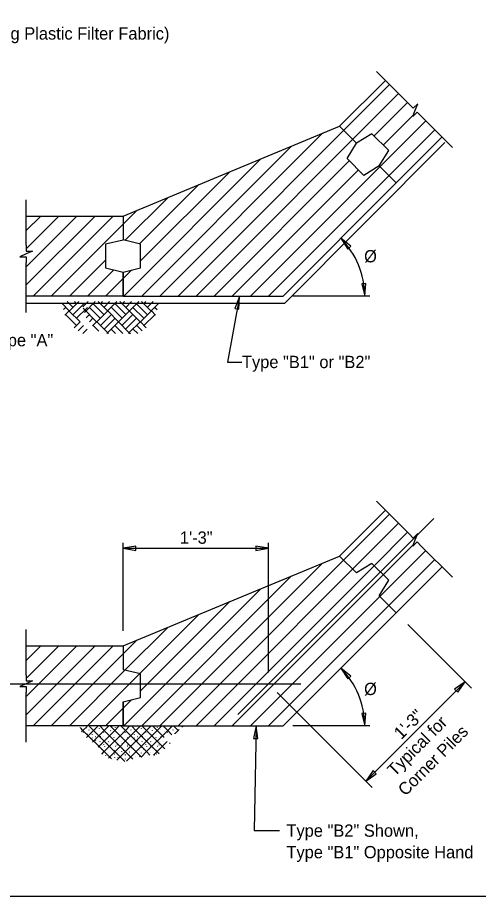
# Model space of a CAD drawing. Extents: x 111162.5 to 111216.6, y 110741.1 to 110776.1.
# Drawn here: x 111173.58 to 111179.25, y 110754.44 to 110765.24 of the extents above; entities that cross this region are included whole.
import ezdxf

# ---------------------------------------------------------------- set-up
doc = ezdxf.new("R2010")
doc.units = 0
for name, color, linetype in [('Patterning', 7, 'Continuous'), ('PlotBorder_dp', 7, 'Continuous'), ('SheetBorder_dp', 7, 'Continuous'), ('TextMisc', 7, 'Continuous'), ('Viewport', 7, 'Continuous')]:
    doc.layers.add(name, color=color, linetype=linetype)

msp = doc.modelspace()

# ---------------------------------------------------------------- linework, layer by layer
at = {"layer": 'Patterning'}
for p, q in [((111177.998, 110764.581), (111178.4, 110764.179)), ((111178.549, 110764.03), (111178.931, 110763.648)), ((111176.868, 110761.733), (111178.84, 110763.706)), ((111173.687, 110762.444), (111173.687, 110763.004)), ((111173.687, 110761.618), (111173.687, 110762.233)), ((111173.687, 110761.733), (111176.868, 110761.733)), ((111177.916, 110761.819), (111176.967, 110761.819)), ((111177.998, 110759.297), (111178.4, 110758.895)), ((111174.879, 110757.705), (111174.879, 110758.784)), ((111174.879, 110758.718), (111176.669, 110758.718)), ((111176.669, 110757.192), (111176.669, 110758.784)), ((111178.549, 110758.746), (111178.931, 110758.364)), ((111178.385, 110757.782), (111179.167, 110756.999)), ((111173.687, 110757.16), (111173.687, 110757.72)), ((111177.866, 110755.855), (111179.089, 110757.078)), ((111173.687, 110756.333), (111173.687, 110756.949)), ((111176.774, 110756.947), (111177.945, 110755.777)), ((111177.916, 110756.535), (111176.967, 110756.535))]:
    msp.add_line(p, q, dxfattribs=at)
for points in [[(111178.549, 110764.03), (111178.498, 110764.082), (111178.443, 110764.027), (111178.474, 110764.105), (111178.505, 110764.184), (111178.45, 110764.129), (111178.399, 110764.181)], [(111173.687, 110762.444), (111173.687, 110762.371), (111173.765, 110762.371), (111173.687, 110762.337), (111173.61, 110762.304), (111173.687, 110762.304), (111173.687, 110762.231)], [(111176.31, 110761.815), (111176.164, 110761.007), (111176.341, 110761.007)], [(111178.549, 110758.746), (111178.498, 110758.797), (111178.443, 110758.743), (111178.474, 110758.821), (111178.505, 110758.9), (111178.45, 110758.845), (111178.399, 110758.896)], [(111173.687, 110757.159), (111173.687, 110757.087), (111173.765, 110757.087), (111173.687, 110757.053), (111173.61, 110757.019), (111173.687, 110757.019), (111173.687, 110756.947)], [(111176.517, 110756.535), (111176.493, 110755.249), (111176.804, 110755.249)]]:
    msp.add_lwpolyline(points, dxfattribs=at)
for points in [[(111177.559, 110762.53), (111177.643, 110762.397), (111177.683, 110762.432)], [(111177.854, 110761.819), (111177.868, 110761.976), (111177.816, 110761.972)], [(111176.31, 110761.815), (111176.254, 110761.667), (111176.305, 110761.657)], [(111174.879, 110758.718), (111175.035, 110758.692), (111175.035, 110758.744)], [(111176.669, 110758.718), (111176.513, 110758.744), (111176.513, 110758.692)], [(111177.559, 110757.246), (111177.643, 110757.112), (111177.683, 110757.148)], [(111179.089, 110757.078), (111178.959, 110756.986), (111178.997, 110756.949)], [(111177.854, 110756.534), (111177.868, 110756.692), (111177.816, 110756.688)], [(111176.517, 110756.535), (111176.486, 110756.38), (111176.539, 110756.378)], [(111177.866, 110755.855), (111177.995, 110755.947), (111177.958, 110755.985)]]:
    msp.add_lwpolyline(points, close=True, dxfattribs=at)
for centre in [(111176.847, 110761.819), (111176.847, 110756.535)]:
    msp.add_arc(centre, 1.005, 0, 45.0008, dxfattribs=at)
at = {"layer": 'PlotBorder_dp'}
for p, q in [((111177.543, 110763.908), (111178.107, 110764.472)), ((111174.879, 110762.804), (111177.543, 110763.908)), ((111177.543, 110763.908), (111177.752, 110763.699)), ((111177.752, 110763.699), (111177.543, 110763.908)), ((111177.543, 110763.908), (111177.752, 110763.699)), ((111177.942, 110763.816), (111177.752, 110763.699)), ((111178.148, 110763.61), (111177.942, 110763.816)), ((111177.635, 110763.509), (111177.752, 110763.699)), ((111178.804, 110763.776), (111178.239, 110763.212)), ((111178.031, 110763.42), (111178.148, 110763.61)), ((111177.841, 110763.303), (111177.635, 110763.509)), ((111178.031, 110763.42), (111177.841, 110763.303)), ((111178.031, 110763.42), (111178.239, 110763.212)), ((111178.239, 110763.212), (111178.031, 110763.42)), ((111178.239, 110763.212), (111178.031, 110763.42)), ((111176.847, 110761.819), (111178.239, 110763.212)), ((111173.687, 110762.804), (111174.879, 110762.804)), ((111174.879, 110762.804), (111174.879, 110762.509)), ((111174.879, 110762.804), (111174.879, 110762.508)), ((111174.879, 110762.508), (111174.662, 110762.457)), ((111175.095, 110762.457), (111174.879, 110762.509)), ((111174.662, 110762.457), (111174.662, 110762.166)), ((111175.095, 110762.166), (111175.095, 110762.457)), ((111174.662, 110762.166), (111174.879, 110762.115)), ((111174.879, 110762.115), (111175.095, 110762.166)), ((111174.879, 110762.115), (111174.879, 110761.819)), ((111174.879, 110761.819), (111174.879, 110762.115)), ((111174.879, 110761.819), (111173.687, 110761.819)), ((111174.879, 110761.819), (111176.847, 110761.819)), ((111177.543, 110758.623), (111178.107, 110759.188)), ((111174.879, 110757.52), (111177.543, 110758.623)), ((111177.543, 110758.623), (111177.752, 110758.415)), ((111177.752, 110758.415), (111177.543, 110758.623)), ((111177.543, 110758.623), (111177.752, 110758.415)), ((111177.942, 110758.532), (111177.752, 110758.415)), ((111178.148, 110758.326), (111177.942, 110758.532)), ((111178.804, 110758.491), (111178.239, 110757.927)), ((111178.031, 110758.136), (111178.148, 110758.326)), ((111178.031, 110758.136), (111178.239, 110757.927)), ((111178.239, 110757.927), (111178.031, 110758.136)), ((111178.239, 110757.927), (111178.031, 110758.136)), ((111176.847, 110756.535), (111178.239, 110757.927)), ((111173.687, 110757.52), (111174.879, 110757.52)), ((111174.879, 110757.52), (111174.879, 110757.224)), ((111174.879, 110757.52), (111174.879, 110757.224)), ((111175.095, 110757.173), (111174.879, 110757.224)), ((111175.095, 110756.882), (111175.095, 110757.173)), ((111174.879, 110756.831), (111175.095, 110756.882)), ((111174.879, 110756.831), (111174.879, 110756.535)), ((111174.879, 110756.535), (111174.879, 110756.831)), ((111174.879, 110756.535), (111173.687, 110756.535)), ((111174.879, 110756.535), (111176.847, 110756.535))]:
    msp.add_line(p, q, dxfattribs=at)
at = {"layer": 'TextMisc'}
for p, q in [((111175.555, 110761.819), (111178.157, 110764.422)), ((111175.778, 110761.819), (111178.269, 110764.31)), ((111177.969, 110763.788), (111178.38, 110764.199)), ((111178.08, 110763.677), (111178.452, 110764.048)), ((111176.446, 110761.819), (111178.603, 110763.976)), ((111175.332, 110761.819), (111177.333, 110763.821)), ((111176.669, 110761.819), (111178.714, 110763.865)), ((111175.109, 110761.819), (111176.953, 110763.663)), ((111174.887, 110761.819), (111176.573, 110763.506)), ((111176, 110761.819), (111177.663, 110763.482)), ((111175.095, 110762.251), (111176.193, 110763.348)), ((111176.223, 110761.819), (111177.774, 110763.371)), ((111175.082, 110762.46), (111175.812, 110763.191)), ((111174.902, 110762.503), (111175.432, 110763.033)), ((111173.996, 110761.819), (111175.052, 110762.876)), ((111173.687, 110762.179), (111174.312, 110762.804)), ((111173.687, 110761.956), (111174.535, 110762.804)), ((111173.687, 110762.625), (111173.866, 110762.804)), ((111173.687, 110762.402), (111174.089, 110762.804)), ((111173.773, 110761.819), (111174.757, 110762.804)), ((111174.218, 110761.819), (111174.662, 110762.263)), ((111174.441, 110761.819), (111174.764, 110762.142)), ((111174.664, 110761.819), (111174.984, 110762.14)), ((111174.128, 110761.729), (111174.217, 110761.639)), ((111174.193, 110761.751), (111174.261, 110761.683)), ((111174.335, 110761.751), (111174.22, 110761.637)), ((111174.396, 110761.724), (111174.264, 110761.592)), ((111174.282, 110761.751), (111174.306, 110761.728)), ((111174.383, 110761.686), (111174.448, 110761.751)), ((111174.537, 110761.751), (111174.403, 110761.617)), ((111174.51, 110761.724), (111174.642, 110761.592)), ((111174.571, 110761.751), (111174.686, 110761.637)), ((111174.624, 110761.751), (111174.601, 110761.728)), ((111174.713, 110761.751), (111174.645, 110761.683)), ((111174.801, 110761.751), (111174.689, 110761.639)), ((111174.78, 110761.725), (111174.913, 110761.592)), ((111175.072, 110761.751), (111174.824, 110761.504)), ((111174.841, 110761.751), (111175.089, 110761.504)), ((111174.868, 110761.724), (111174.895, 110761.751)), ((111174.912, 110761.68), (111174.983, 110761.751)), ((111175.045, 110761.724), (111175.177, 110761.592)), ((111175.106, 110761.751), (111175.221, 110761.637)), ((111175.159, 110761.751), (111175.136, 110761.728)), ((111175.248, 110761.751), (111175.18, 110761.683)), ((111175.314, 110761.729), (111175.224, 110761.639)), ((111174.17, 110761.681), (111174.145, 110761.655)), ((111174.214, 110761.637), (111174.161, 110761.583)), ((111174.35, 110761.501), (111174.217, 110761.634)), ((111174.441, 110761.68), (111174.308, 110761.548)), ((111174.388, 110761.67), (111174.554, 110761.504)), ((111174.466, 110761.68), (111174.598, 110761.548)), ((111174.556, 110761.501), (111174.689, 110761.634)), ((111174.692, 110761.637), (111174.824, 110761.504)), ((111174.736, 110761.681), (111174.869, 110761.548)), ((111175.001, 110761.68), (111175.133, 110761.548)), ((111175.092, 110761.501), (111175.224, 110761.634)), ((111175.227, 110761.637), (111175.28, 110761.583)), ((111175.271, 110761.681), (111175.297, 110761.655)), ((111174.306, 110761.457), (111174.173, 110761.589)), ((111174.465, 110761.592), (111174.426, 110761.553)), ((111174.509, 110761.548), (111174.464, 110761.503)), ((111174.601, 110761.457), (111174.733, 110761.589)), ((111174.645, 110761.413), (111174.777, 110761.545)), ((111175, 110761.592), (111174.868, 110761.46)), ((111175.045, 110761.548), (111174.912, 110761.416)), ((111175.136, 110761.457), (111175.268, 110761.589)), ((111174.35, 110761.501), (111174.276, 110761.428)), ((111174.394, 110761.457), (111174.328, 110761.392)), ((111174.438, 110761.413), (111174.382, 110761.358)), ((111174.554, 110761.504), (111174.503, 110761.453)), ((111174.513, 110761.457), (111174.582, 110761.388)), ((111174.556, 110761.501), (111174.698, 110761.359)), ((111174.822, 110761.501), (111174.678, 110761.358)), ((111174.733, 110761.413), (111174.788, 110761.358)), ((111174.777, 110761.457), (111174.876, 110761.358)), ((111174.822, 110761.501), (111174.954, 110761.369)), ((111175.089, 110761.504), (111174.956, 110761.372)), ((111175.004, 110761.413), (111175.059, 110761.358)), ((111175.048, 110761.457), (111175.113, 110761.392)), ((111175.092, 110761.501), (111175.165, 110761.428)), ((111174.948, 110761.358), (111174.956, 110761.366)), ((111174.959, 110761.369), (111174.971, 110761.358)), ((111175.555, 110756.535), (111178.157, 110759.138)), ((111175.778, 110756.535), (111178.269, 110759.026)), ((111178.701, 110759.085), (111176.291, 110756.675)), ((111177.969, 110758.504), (111178.38, 110758.915)), ((111178.08, 110758.393), (111178.452, 110758.764)), ((111176, 110756.535), (111178.086, 110758.62)), ((111176.446, 110756.535), (111178.603, 110758.692)), ((111175.332, 110756.535), (111177.333, 110758.536)), ((111176.669, 110756.535), (111178.714, 110758.581)), ((111175.109, 110756.535), (111176.953, 110758.379)), ((111176.223, 110756.535), (111178.08, 110758.393)), ((111174.887, 110756.535), (111176.573, 110758.221)), ((111175.095, 110756.967), (111176.193, 110758.064)), ((111175.082, 110757.176), (111175.812, 110757.906)), ((111174.902, 110757.219), (111175.432, 110757.749)), ((111173.687, 110756.895), (111174.312, 110757.52)), ((111173.687, 110756.672), (111174.535, 110757.52)), ((111173.687, 110757.34), (111173.866, 110757.52)), ((111173.687, 110757.118), (111174.089, 110757.52)), ((111173.773, 110756.535), (111174.757, 110757.52)), ((111173.996, 110756.535), (111175.052, 110757.591)), ((111174.218, 110756.535), (111174.902, 110757.219)), ((111174.441, 110756.535), (111175.095, 110757.189)), ((111173.293, 110757.053), (111173.687, 110757.053)), ((111173.687, 110757.053), (111177.065, 110757.053)), ((111174.664, 110756.535), (111174.984, 110756.856)), ((111174.356, 110756.517), (111174.356, 110756.52)), ((111174.386, 110756.479), (111174.358, 110756.507)), ((111174.369, 110756.461), (111174.386, 110756.479)), ((111174.386, 110756.479), (111174.437, 110756.529)), ((111174.647, 110756.218), (111174.386, 110756.479)), ((111174.393, 110756.453), (111174.394, 110756.456)), ((111174.428, 110756.509), (111174.426, 110756.51)), ((111174.429, 110756.392), (111174.517, 110756.479)), ((111174.441, 110756.436), (111174.437, 110756.435)), ((111174.462, 110756.482), (111174.459, 110756.481)), ((111174.517, 110756.479), (111174.466, 110756.529)), ((111174.483, 110756.438), (111174.481, 110756.44)), ((111174.494, 110756.501), (111174.493, 110756.502)), ((111174.501, 110756.333), (111174.647, 110756.479)), ((111174.501, 110756.431), (111174.503, 110756.434)), ((111174.517, 110756.479), (111174.567, 110756.53)), ((111174.647, 110756.349), (111174.517, 110756.479)), ((111174.531, 110756.484), (111174.531, 110756.487)), ((111174.588, 110756.5), (111174.589, 110756.503)), ((111174.647, 110756.479), (111174.596, 110756.53)), ((111174.618, 110756.44), (111174.618, 110756.443)), ((111174.624, 110756.493), (111174.625, 110756.496)), ((111174.643, 110756.455), (111174.644, 110756.458)), ((111174.647, 110756.479), (111174.698, 110756.53)), ((111175.001, 110756.124), (111174.647, 110756.479)), ((111174.647, 110756.218), (111174.907, 110756.479)), ((111174.647, 110756.349), (111174.777, 110756.479)), ((111174.698, 110756.139), (111175.037, 110756.479)), ((111174.725, 110756.474), (111174.727, 110756.477)), ((111174.725, 110756.426), (111174.727, 110756.429)), ((111174.777, 110756.479), (111174.726, 110756.53)), ((111174.745, 110756.525), (111174.741, 110756.524)), ((111174.769, 110756.44), (111174.769, 110756.443)), ((111174.777, 110756.479), (111174.829, 110756.53)), ((111175.104, 110756.152), (111174.777, 110756.479)), ((111174.787, 110756.512), (111174.786, 110756.514)), ((111174.787, 110756.465), (111174.786, 110756.466)), ((111174.801, 110756.112), (111175.168, 110756.479)), ((111174.818, 110756.489), (111174.818, 110756.492)), ((111174.907, 110756.479), (111174.856, 110756.531)), ((111174.872, 110756.516), (111174.873, 110756.52)), ((111174.872, 110756.469), (111174.873, 110756.472)), ((111174.907, 110756.479), (111174.959, 110756.531)), ((111175.168, 110756.218), (111174.907, 110756.479)), ((111174.91, 110756.453), (111174.911, 110756.456)), ((111174.945, 110756.509), (111174.943, 110756.51)), ((111174.957, 110756.436), (111174.954, 110756.435)), ((111174.979, 110756.482), (111174.976, 110756.481)), ((111175.037, 110756.479), (111174.985, 110756.531)), ((111175, 110756.438), (111174.998, 110756.44)), ((111175.011, 110756.501), (111175.01, 110756.502)), ((111175.018, 110756.431), (111175.02, 110756.434)), ((111175.037, 110756.479), (111175.09, 110756.531)), ((111175.168, 110756.349), (111175.037, 110756.479)), ((111175.048, 110756.484), (111175.048, 110756.487)), ((111175.105, 110756.5), (111175.106, 110756.503)), ((111175.167, 110756.479), (111175.115, 110756.531)), ((111175.134, 110756.44), (111175.135, 110756.443)), ((111175.141, 110756.493), (111175.142, 110756.496)), ((111175.16, 110756.455), (111175.161, 110756.458)), ((111175.168, 110756.479), (111175.221, 110756.532)), ((111175.392, 110756.254), (111175.168, 110756.479)), ((111175.168, 110756.218), (111175.428, 110756.479)), ((111175.168, 110756.349), (111175.298, 110756.479)), ((111175.242, 110756.474), (111175.243, 110756.477)), ((111175.242, 110756.426), (111175.243, 110756.429)), ((111175.298, 110756.479), (111175.245, 110756.532)), ((111175.262, 110756.525), (111175.258, 110756.524)), ((111175.286, 110756.44), (111175.286, 110756.443)), ((111175.298, 110756.479), (111175.351, 110756.532)), ((111175.384, 110756.393), (111175.298, 110756.479)), ((111175.304, 110756.512), (111175.303, 110756.514)), ((111175.304, 110756.465), (111175.303, 110756.466)), ((111175.334, 110756.489), (111175.335, 110756.492)), ((111175.428, 110756.479), (111175.375, 110756.532)), ((111175.389, 110756.516), (111175.39, 110756.52)), ((111175.389, 110756.469), (111175.39, 110756.472)), ((111175.427, 110756.453), (111175.428, 110756.456)), ((111175.428, 110756.479), (111175.482, 110756.533)), ((111175.481, 110756.426), (111175.428, 110756.479)), ((111175.462, 110756.509), (111175.46, 110756.51)), ((111175.474, 110756.436), (111175.471, 110756.435)), ((111175.496, 110756.482), (111175.493, 110756.481)), ((111175.558, 110756.479), (111175.504, 110756.533)), ((111175.516, 110756.439), (111175.515, 110756.44)), ((111175.52, 110756.44), (111175.558, 110756.479)), ((111175.528, 110756.501), (111175.527, 110756.502)), ((111175.558, 110756.479), (111175.57, 110756.49)), ((111175.563, 110756.475), (111175.558, 110756.479)), ((111175.565, 110756.484), (111175.565, 110756.487)), ((111175.602, 110756.523), (111175.613, 110756.533)), ((111174.501, 110756.383), (111174.503, 110756.387)), ((111174.545, 110756.402), (111174.541, 110756.401)), ((111174.545, 110756.354), (111174.541, 110756.353)), ((111174.572, 110756.274), (111174.647, 110756.349)), ((111174.598, 110756.338), (111174.599, 110756.341)), ((111174.604, 110756.402), (111174.6, 110756.401)), ((111174.643, 110756.407), (111174.644, 110756.41)), ((111174.899, 110756.097), (111174.647, 110756.349)), ((111174.669, 110756.369), (111174.664, 110756.369)), ((111174.703, 110756.34), (111174.701, 110756.341)), ((111174.73, 110756.399), (111174.727, 110756.399)), ((111174.769, 110756.393), (111174.769, 110756.396)), ((111174.778, 110756.341), (111174.778, 110756.344)), ((111174.807, 110756.346), (111174.806, 110756.347)), ((111174.828, 110756.398), (111174.824, 110756.397)), ((111174.86, 110756.341), (111174.86, 110756.344)), ((111174.887, 110756.37), (111174.89, 110756.373)), ((111174.887, 110756.323), (111174.89, 110756.326)), ((111174.922, 110756.103), (111175.168, 110756.349)), ((111174.936, 110756.388), (111174.938, 110756.391)), ((111174.938, 110756.387), (111174.939, 110756.39)), ((111174.979, 110756.358), (111174.978, 110756.36)), ((111175.018, 110756.326), (111175.017, 110756.327)), ((111175.018, 110756.383), (111175.02, 110756.387)), ((111175.021, 110756.328), (111175.018, 110756.328)), ((111175.062, 110756.402), (111175.058, 110756.401)), ((111175.062, 110756.354), (111175.058, 110756.353)), ((111175.115, 110756.338), (111175.116, 110756.341)), ((111175.121, 110756.402), (111175.117, 110756.401)), ((111175.16, 110756.407), (111175.161, 110756.41)), ((111175.325, 110756.192), (111175.168, 110756.349)), ((111175.186, 110756.369), (111175.181, 110756.369)), ((111175.219, 110756.34), (111175.218, 110756.341)), ((111175.247, 110756.399), (111175.244, 110756.399)), ((111175.252, 110756.173), (111175.421, 110756.342)), ((111175.286, 110756.393), (111175.286, 110756.396)), ((111175.295, 110756.341), (111175.295, 110756.344)), ((111175.324, 110756.346), (111175.323, 110756.347)), ((111175.345, 110756.398), (111175.341, 110756.397)), ((111175.377, 110756.341), (111175.377, 110756.344)), ((111175.404, 110756.323), (111175.407, 110756.326)), ((111175.46, 110756.317), (111175.452, 110756.325)), ((111174.597, 110756.265), (111174.598, 110756.269)), ((111174.616, 110756.312), (111174.612, 110756.311)), ((111174.618, 110756.189), (111174.647, 110756.219)), ((111174.623, 110756.29), (111174.622, 110756.29)), ((111174.623, 110756.242), (111174.622, 110756.244)), ((111174.642, 110756.303), (111174.642, 110756.306)), ((111174.736, 110756.129), (111174.647, 110756.219)), ((111174.653, 110756.281), (111174.654, 110756.285)), ((111174.686, 110756.31), (111174.687, 110756.313)), ((111174.703, 110756.278), (111174.705, 110756.281)), ((111174.727, 110756.265), (111174.724, 110756.265)), ((111174.773, 110756.234), (111174.771, 110756.236)), ((111174.787, 110756.281), (111174.783, 110756.28)), ((111174.807, 110756.299), (111174.806, 110756.3)), ((111174.813, 110756.247), (111174.814, 110756.25)), ((111174.86, 110756.317), (111174.86, 110756.32)), ((111174.863, 110756.267), (111174.864, 110756.271)), ((111174.863, 110756.22), (111174.864, 110756.223)), ((111174.89, 110756.228), (111174.89, 110756.231)), ((111174.934, 110756.284), (111174.936, 110756.287)), ((111174.938, 110756.299), (111174.939, 110756.302)), ((111174.966, 110756.293), (111174.968, 110756.297)), ((111174.986, 110756.261), (111174.987, 110756.264)), ((111175.004, 110756.239), (111175.002, 110756.24)), ((111175.051, 110756.276), (111175.053, 110756.279)), ((111175.051, 110756.229), (111175.053, 110756.232)), ((111175.081, 110756.227), (111175.082, 110756.23)), ((111175.1, 110756.151), (111175.168, 110756.219)), ((111175.114, 110756.265), (111175.114, 110756.269)), ((111175.133, 110756.312), (111175.129, 110756.311)), ((111175.14, 110756.29), (111175.139, 110756.29)), ((111175.14, 110756.242), (111175.139, 110756.244)), ((111175.158, 110756.303), (111175.159, 110756.306)), ((111175.209, 110756.177), (111175.168, 110756.219)), ((111175.17, 110756.281), (111175.171, 110756.285)), ((111175.203, 110756.31), (111175.204, 110756.313)), ((111175.22, 110756.278), (111175.222, 110756.281)), ((111175.244, 110756.265), (111175.241, 110756.265)), ((111175.29, 110756.234), (111175.288, 110756.236)), ((111175.304, 110756.281), (111175.3, 110756.28)), ((111175.324, 110756.299), (111175.323, 110756.3)), ((111175.33, 110756.247), (111175.331, 110756.25)), ((111175.377, 110756.317), (111175.377, 110756.32)), ((111175.38, 110756.267), (111175.381, 110756.271)), ((111174.667, 110756.171), (111174.668, 110756.174)), ((111174.703, 110756.206), (111174.704, 110756.209)), ((111174.751, 110756.174), (111174.747, 110756.173)), ((111174.751, 110756.126), (111174.748, 110756.126)), ((111174.773, 110756.187), (111174.771, 110756.189)), ((111174.778, 110756.144), (111174.778, 110756.147)), ((111174.814, 110756.21), (111174.815, 110756.213)), ((111174.818, 110756.144), (111174.818, 110756.147)), ((111174.853, 110756.149), (111174.854, 110756.152)), ((111174.909, 110756.174), (111174.91, 110756.178)), ((111174.909, 110756.127), (111174.91, 110756.13)), ((111174.91, 110756.18), (111174.911, 110756.183)), ((111174.962, 110756.211), (111174.958, 110756.21)), ((111174.965, 110756.142), (111174.962, 110756.141)), ((111174.963, 110756.173), (111174.964, 110756.176)), ((111174.987, 110756.144), (111174.988, 110756.147)), ((111175.004, 110756.192), (111175.002, 110756.193)), ((111175.036, 110756.157), (111175.037, 110756.16)), ((111175.083, 110756.155), (111175.084, 110756.158)), ((111175.105, 110756.199), (111175.105, 110756.202)), ((111175.185, 110756.174), (111175.185, 110756.174)), ((111175.22, 110756.206), (111175.221, 110756.209)), ((111175.268, 110756.174), (111175.264, 110756.173)), ((111175.29, 110756.187), (111175.288, 110756.189)), ((111175.331, 110756.21), (111175.331, 110756.213))]:
    msp.add_line(p, q, dxfattribs=at)
at = {"layer": 'Viewport'}
msp.add_lwpolyline([(111162.551, 110774.238), (111193.351, 110774.238), (111193.351, 110754.438), (111162.551, 110754.438)], close=True, dxfattribs=at)

# ---------------------------------------------------------------- texts
at = {"layer": 'Patterning'}
for s, p in [('1\'-3"', (111178.302, 110756.36)), ('Typical for', (111178.221, 110755.905)), ('Corner Piles', (111178.353, 110755.664))]:
    msp.add_text(s, height=0.1512, rotation=45, dxfattribs=at).set_placement(p)
at = {"layer": 'SheetBorder_dp'}
for s, height, p in [('(Showing Plastic Filter Fabric)', 0.1512, (111172.764, 110764.973)), ('Ø', 0.151, (111177.845, 110762.234)), ('Type "A"', 0.1512, (111173.236, 110761.202)), ('Type "B1" or "B2"', 0.1512, (111176.342, 110760.934)), ('1\'-3"', 0.1512, (111175.578, 110758.774)), ('Ø', 0.151, (111177.845, 110756.914)), ('Type "B2" Shown,', 0.1512, (111176.889, 110755.172)), ('Type "B1" Opposite Hand', 0.1512, (111176.889, 110754.907))]:
    msp.add_text(s, height=height, dxfattribs=at).set_placement(p)

doc.saveas('drawing.dxf')
